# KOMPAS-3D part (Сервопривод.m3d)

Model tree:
1. Эскиз:1
2. Операция выдавливания:1
     Расстояние 1 = 31.33
3. Смещенная плоскость:1
     Расстояние = 24.16
4. Эскиз:2
5. Операция выдавливания:2
     Расстояние 1 = 2.1
6. Эскиз:3
7. Операция выдавливания:3
     Расстояние 1 = 20; Расстояние 2 = 20
8. Эскиз:4
9. Операция вращения:1
     Угол 1 = 360
10. Смещенная плоскость:2
     Расстояние = 1
11. Эскиз:5
12. Операция выдавливания:4
     Расстояние 1 = 20; Расстояние 2 = 5; Угол 2 = 23
13. Эскиз:6
14. Вырезать элемент выдавливания:1
     Расстояние 1 = 3
15. Эскиз:7
16. Операция выдавливания:5
     Расстояние 1 = 41.08; Расстояние 2 = 41.08
17. Скругление:1
     Радиус = 1
18. Скругление:2
     Радиус = 1
19. Скругление:3
     Радиус = 1
20. Эскиз:8
21. Операция выдавливания:6
     Расстояние 1 = 5.75; Угол 1 = 8; Расстояние 2 = 41.08
22. Эскиз:9
23. Операция выдавливания:7
     Расстояние 1 = 5; Расстояние 2 = 41.08
24. Скругление:4
     Радиус = 0.2
25. Ось конической поверхности:1
26. Эскиз:10
27. Вырезать элемент выдавливания:2
     Расстояние 1 = 5
28. Вырезать элемент выдавливания:3
     Расстояние 1 = 5
29. Эскиз:12
30. Вырезать элемент вращения:1
     Угол 1 = 360
31. Эскиз:13
32. Вырезать элемент выдавливания:4
     Расстояние 1 = 10
